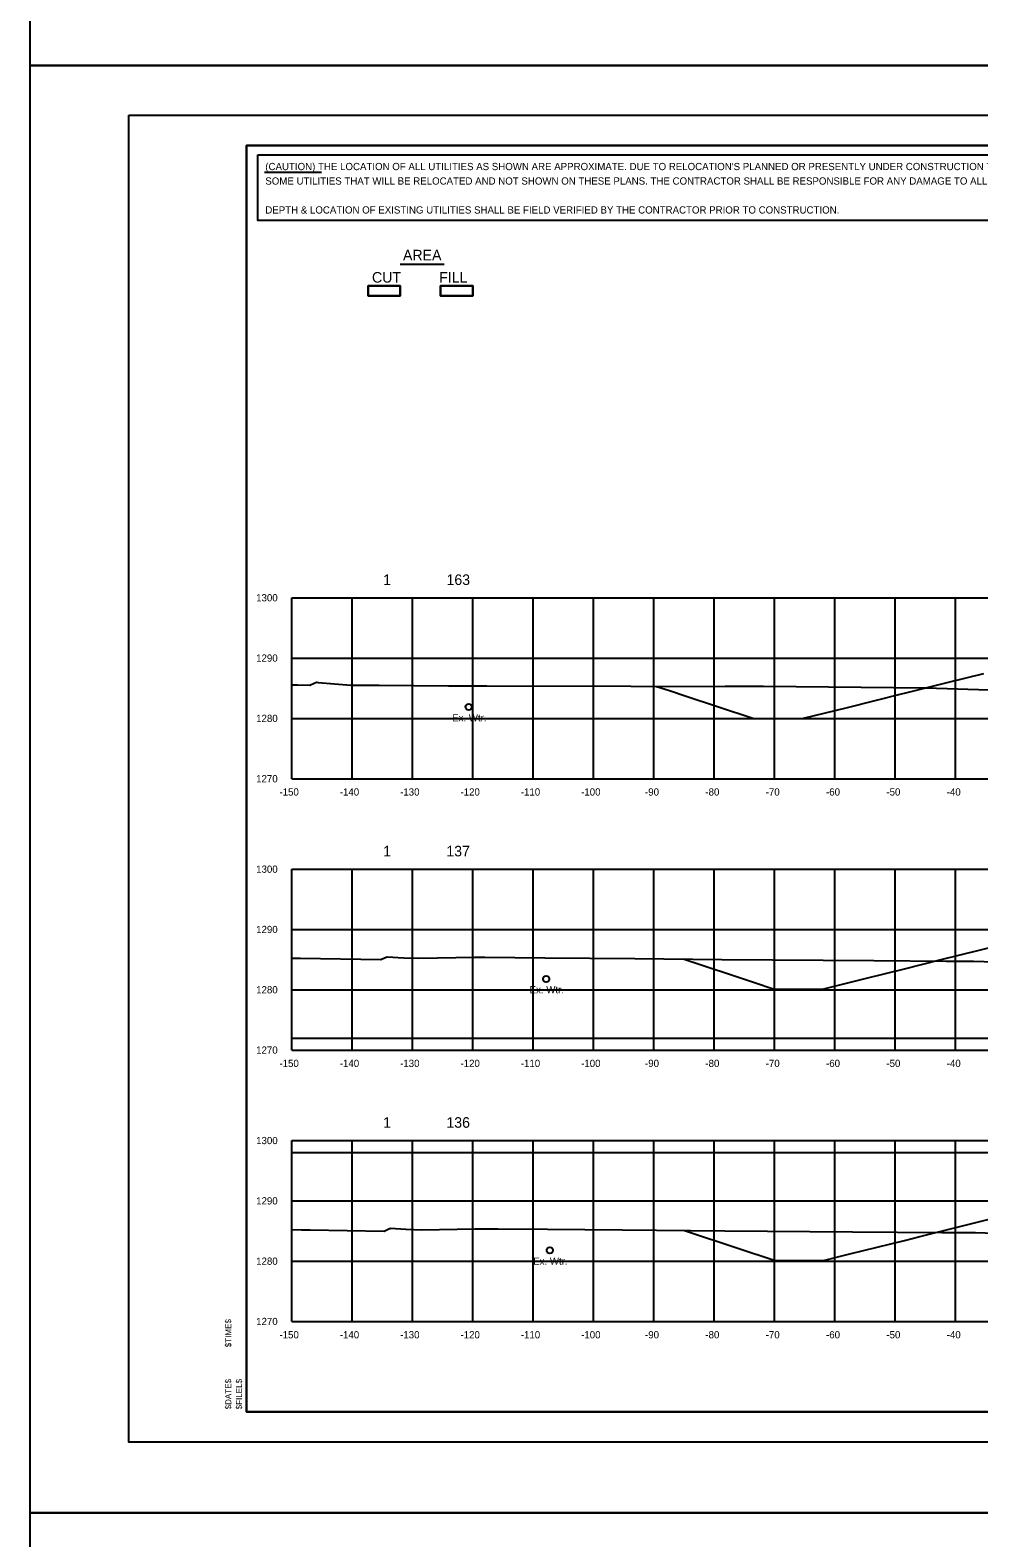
# Model space of a CAD drawing. Extents: x 2148105 to 2149976, y 144169 to 149705.
# Drawn here: x 2148219.9 to 2148377.2, y 144421 to 144671 of the extents above; entities that cross this region are included whole.
import ezdxf

# ---------------------------------------------------------------- set-up
doc = ezdxf.new("R2010")
doc.units = 0
for name, color, linetype in [('EX_Align', 7, 'Continuous'), ('PH1a-PR-Drives', 7, 'Continuous'), ('PH1a-PR-ServRd', 7, 'Continuous'), ('PH1a-TempConn-Shld', 7, 'Continuous'), ('PR_Align_PC', 7, 'Continuous'), ('PR_Align_Ramp_E', 7, 'Continuous'), ('PR_Align_Ramp_J', 7, 'Continuous'), ('PR_Storm_Conc_Box_PH1B', 7, 'Continuous'), ('PR_Storm_Conc_Pipe_PH1B', 7, 'Continuous'), ('PR_Storm_Inlet_CICI_PH1B', 7, 'Continuous'), ('PR_Storm_Junction_Box_PH1A', 7, 'Continuous'), ('PR_Storm_MH', 7, 'Continuous'), ('PR_Storm_MH_PH1B', 7, 'Continuous'), ('PR_Storm_Standard_Median_Drain_PH1B', 7, 'Continuous'), ('SURV_Benchmark', 7, 'Continuous'), ('TopCut', 7, 'Continuous'), ('TOPO_Asphalt', 7, 'Continuous'), ('TOPO_BRIDGE_Pier Cap', 7, 'Continuous')]:
    doc.layers.add(name, color=color, linetype=linetype)

msp = doc.modelspace()

# ---------------------------------------------------------------- linework, layer by layer
at = {"layer": 'EX_Align'}
for points in [[(2148323.77, 144562.22), (2148325.88, 144561.52), (2148328.67, 144560.6), (2148333.88, 144558.87), (2148339.89, 144556.87), (2148340.5, 144556.87), (2148342.6, 144556.87), (2148343.72, 144556.87), (2148343.91, 144556.87), (2148347.15, 144556.87), (2148347.92, 144556.87), (2148355.43, 144558.74), (2148364.35, 144560.97), (2148365.08, 144561.15), (2148366.16, 144561.42), (2148372.17, 144562.92), (2148377.99, 144564.37)], [(2148328.18, 144517.02), (2148339.97, 144513.1), (2148343.26, 144512), (2148346.06, 144512), (2148347.26, 144512), (2148349.86, 144512), (2148351.27, 144512), (2148358.53, 144513.82), (2148364.83, 144515.39), (2148370.71, 144516.86), (2148380.81, 144519.38), (2148381.26, 144519.36), (2148382.83, 144519.3), (2148384.48, 144519.23), (2148384.83, 144519.22), (2148385.47, 144519.19), (2148388.83, 144519.05), (2148389.99, 144519.01), (2148396.75, 144518.73), (2148400.83, 144518.56)], [(2148328.39, 144472.01), (2148337.21, 144469.07), (2148343.4, 144467.01), (2148345.29, 144467.01), (2148347.41, 144467.01), (2148349.09, 144467.01), (2148351.41, 144467.01), (2148355.8, 144468.11), (2148364.84, 144470.36), (2148367.38, 144471), (2148378.21, 144473.7), (2148379.56, 144474.04), (2148380.84, 144474.36), (2148382.35, 144474.29), (2148382.85, 144474.27), (2148384.13, 144474.22), (2148384.85, 144474.19), (2148386.78, 144474.11), (2148388.85, 144474.03), (2148391.34, 144473.92), (2148394.72, 144473.78), (2148399.86, 144473.57), (2148400.85, 144473.53)]]:
    msp.add_lwpolyline(points, dxfattribs=at)
at = {"layer": 'PH1a-PR-ServRd'}
msp.add_lwpolyline([(2148570.82, 144441.91), (2148255.82, 144441.91), (2148255.82, 144651.91), (2148570.82, 144651.91)], close=True, dxfattribs=at)
at = {"layer": 'PH1a-TempConn-Shld'}
msp.add_line((2148263.32, 144503.91), (2148563.32, 144503.91), dxfattribs=at)
at = {"layer": 'PR_Align_PC'}
msp.add_line((2148281.28, 144632.21), (2148288.56, 144632.21), dxfattribs=at)
for points in [[(2148275.98, 144628.66), (2148281.29, 144628.66), (2148281.29, 144626.97), (2148275.98, 144626.97)], [(2148275.98, 144628.66), (2148281.29, 144628.66), (2148281.29, 144626.97), (2148275.98, 144626.97)], [(2148287.98, 144628.66), (2148293.29, 144628.66), (2148293.29, 144626.97), (2148287.98, 144626.97)], [(2148287.98, 144628.66), (2148293.29, 144628.66), (2148293.29, 144626.97), (2148287.98, 144626.97)]]:
    msp.add_lwpolyline(points, close=True, dxfattribs=at)
at = {"layer": 'PR_Align_Ramp_E'}
for points in [[(2148219.95, 144905.16), (2148579.95, 144905.16), (2148579.95, 144665.16), (2148219.95, 144665.16)], [(2148219.95, 144665.16), (2148579.95, 144665.16), (2148579.95, 144425.16), (2148219.95, 144425.16)], [(2148219.95, 144425.16), (2148579.95, 144425.16), (2148579.95, 144185.16), (2148219.95, 144185.16)]]:
    msp.add_lwpolyline(points, close=True, dxfattribs=at)
at = {"layer": 'PR_Align_Ramp_J'}
msp.add_lwpolyline([(2148236.32, 144656.91), (2148576.32, 144656.91), (2148576.32, 144436.91), (2148236.32, 144436.91)], close=True, dxfattribs=at)
at = {"layer": 'PR_Storm_Conc_Box_PH1B'}
for p, q in [((2148263.32, 144576.91), (2148563.32, 144576.91)), ((2148263.32, 144546.91), (2148263.32, 144576.91)), ((2148273.32, 144546.91), (2148273.32, 144576.91)), ((2148283.32, 144546.91), (2148283.32, 144576.91)), ((2148293.32, 144546.91), (2148293.32, 144576.91)), ((2148303.32, 144546.91), (2148303.32, 144576.91)), ((2148313.32, 144546.91), (2148313.32, 144576.91)), ((2148323.32, 144546.91), (2148323.32, 144576.91)), ((2148333.32, 144546.91), (2148333.32, 144576.91)), ((2148343.32, 144546.91), (2148343.32, 144576.91)), ((2148353.32, 144546.91), (2148353.32, 144576.91)), ((2148363.32, 144546.91), (2148363.32, 144576.91)), ((2148373.32, 144546.91), (2148373.32, 144576.91)), ((2148263.32, 144566.91), (2148563.32, 144566.91)), ((2148263.32, 144556.91), (2148563.32, 144556.91)), ((2148263.32, 144546.91), (2148563.32, 144546.91)), ((2148263.32, 144531.91), (2148563.32, 144531.91)), ((2148263.32, 144501.91), (2148263.32, 144531.91)), ((2148273.32, 144501.91), (2148273.32, 144531.91)), ((2148283.32, 144501.91), (2148283.32, 144531.91)), ((2148293.32, 144501.91), (2148293.32, 144531.91)), ((2148303.32, 144501.91), (2148303.32, 144531.91)), ((2148313.32, 144501.91), (2148313.32, 144531.91)), ((2148323.32, 144501.91), (2148323.32, 144531.91)), ((2148333.32, 144501.91), (2148333.32, 144531.91)), ((2148343.32, 144501.91), (2148343.32, 144531.91)), ((2148353.32, 144501.91), (2148353.32, 144531.91)), ((2148363.32, 144501.91), (2148363.32, 144531.91)), ((2148373.32, 144501.91), (2148373.32, 144531.91)), ((2148263.32, 144521.91), (2148563.32, 144521.91)), ((2148263.32, 144511.91), (2148563.32, 144511.91)), ((2148263.32, 144501.91), (2148563.32, 144501.91)), ((2148263.32, 144456.91), (2148263.32, 144486.91)), ((2148273.32, 144456.91), (2148273.32, 144486.91)), ((2148283.32, 144456.91), (2148283.32, 144486.91)), ((2148293.32, 144456.91), (2148293.32, 144486.91)), ((2148303.32, 144456.91), (2148303.32, 144486.91)), ((2148313.32, 144456.91), (2148313.32, 144486.91)), ((2148323.32, 144456.91), (2148323.32, 144486.91)), ((2148333.32, 144456.91), (2148333.32, 144486.91)), ((2148343.32, 144456.91), (2148343.32, 144486.91)), ((2148353.32, 144456.91), (2148353.32, 144486.91)), ((2148363.32, 144456.91), (2148363.32, 144486.91)), ((2148373.32, 144456.91), (2148373.32, 144486.91)), ((2148263.32, 144476.91), (2148563.32, 144476.91)), ((2148263.32, 144466.91), (2148563.32, 144466.91)), ((2148263.32, 144456.91), (2148563.32, 144456.91))]:
    msp.add_line(p, q, dxfattribs=at)
at = {"layer": 'PR_Storm_Conc_Pipe_PH1B'}
msp.add_lwpolyline([(2148255.82, 144441.91), (2148570.82, 144441.91), (2148570.82, 144651.91), (2148255.82, 144651.91)], close=True, dxfattribs=at)
msp.add_lwpolyline([(2148255.82, 144441.91), (2148570.82, 144441.91), (2148570.82, 144651.91), (2148255.82, 144651.91)], close=True, dxfattribs=at)
at = {"layer": 'PR_Storm_Inlet_CICI_PH1B'}
for points in [[(2148263.32, 144562.49), (2148264.28, 144562.47), (2148266.3, 144562.43), (2148266.39, 144562.47), (2148267.39, 144562.92), (2148267.69, 144562.87), (2148273.09, 144562.42), (2148277.79, 144562.4), (2148289.26, 144562.32), (2148294.27, 144562.31), (2148295.63, 144562.3), (2148319.47, 144562.26), (2148325.53, 144562.21), (2148335.13, 144562.28), (2148337.19, 144562.27), (2148341.5, 144562.23), (2148368.44, 144561.95), (2148384.04, 144561.46)], [(2148263.32, 144517.17), (2148263.89, 144517.16), (2148264.35, 144517.15), (2148264.76, 144517.15), (2148278.06, 144516.91), (2148278.69, 144517.2), (2148279.14, 144517.4), (2148281.88, 144517.2), (2148284.35, 144517.14), (2148293.58, 144517.29), (2148295.31, 144517.29), (2148305.25, 144517.22), (2148320.18, 144517.11), (2148334.57, 144516.95), (2148359.77, 144516.76), (2148371.74, 144516.67), (2148376.29, 144516.65), (2148399.19, 144515.92)], [(2148263.32, 144472.15), (2148263.32, 144472.15), (2148264.92, 144472.13), (2148266.34, 144472.1), (2148278.61, 144471.89), (2148279.27, 144472.19), (2148279.68, 144472.38), (2148282.21, 144472.19), (2148284.85, 144472.13), (2148293.63, 144472.27), (2148297.51, 144472.27), (2148305.71, 144472.22), (2148318.07, 144472.12), (2148335.05, 144471.93), (2148356.21, 144471.77), (2148371.02, 144471.66), (2148376.64, 144471.64), (2148397.52, 144470.97)]]:
    msp.add_lwpolyline(points, dxfattribs=at)
at = {"layer": 'PR_Storm_Junction_Box_PH1A'}
for centre in [(2148292.63, 144558.8), (2148305.47, 144513.71), (2148306.07, 144468.7)]:
    msp.add_circle(centre, 0.516, dxfattribs=at)
at = {"layer": 'PR_Storm_MH'}
msp.add_line((2148258.8, 144647.46), (2148268.21, 144647.46), dxfattribs=at)
msp.add_lwpolyline([(2148257.69, 144650.34), (2148420.12, 144650.34), (2148420.12, 144639.47), (2148257.69, 144639.47)], close=True, dxfattribs=at)
at = {"layer": 'PR_Storm_Standard_Median_Drain_PH1B'}
for p, q in [((2148263.32, 144546.91), (2148263.32, 144576.91)), ((2148263.32, 144546.91), (2148563.32, 144546.91)), ((2148263.32, 144501.91), (2148263.32, 144531.91)), ((2148263.32, 144501.91), (2148563.32, 144501.91)), ((2148263.32, 144456.91), (2148263.32, 144486.91)), ((2148263.32, 144456.91), (2148563.32, 144456.91))]:
    msp.add_line(p, q, dxfattribs=at)
at = {"layer": 'SURV_Benchmark'}
msp.add_line((2148263.32, 144486.91), (2148563.32, 144486.91), dxfattribs=at)
at = {"layer": 'TopCut'}
msp.add_lwpolyline([(2148287.98, 144626.97), (2148293.29, 144626.97), (2148293.29, 144628.66), (2148287.98, 144628.66), (2148287.98, 144626.97)], dxfattribs=at)
at = {"layer": 'TOPO_Asphalt'}
msp.add_line((2148263.32, 144484.91), (2148563.32, 144484.91), dxfattribs=at)
at = {"layer": 'TOPO_BRIDGE_Pier Cap'}
msp.add_lwpolyline([(2148275.98, 144626.97), (2148281.29, 144626.97), (2148281.29, 144628.66), (2148275.98, 144628.66), (2148275.98, 144626.97)], dxfattribs=at)

# ---------------------------------------------------------------- texts
at = {"layer": 'PH1a-PR-Drives'}
for s, p in [('$TIME$', (2148253.27, 144452.63)), ('$DATE$', (2148253.27, 144442.33)), ('$FILEL$', (2148255.05, 144442.33))]:
    msp.add_text(s, height=1, rotation=90, dxfattribs=at).set_placement(p)
at = {"layer": 'PR_Align_PC'}
for s, p in [('AREA', (2148281.74, 144632.86)), ('CUT', (2148276.6, 144629.17)), ('FILL', (2148287.74, 144629.17)), ('1', (2148278.44, 144579.03)), ('163', (2148288.95, 144579.03)), ('1', (2148278.44, 144534.03)), ('137', (2148288.92, 144534.03)), ('1', (2148278.44, 144489.03)), ('136', (2148288.93, 144489.03))]:
    msp.add_text(s, height=1.75, dxfattribs=at).set_placement(p)
at = {"layer": 'PR_Storm_Junction_Box_PH1A'}
for p in [(2148289.88, 144556.41), (2148302.72, 144511.32), (2148303.31, 144466.31)]:
    msp.add_text('Ex. Wtr.', height=1.2, rotation=360, dxfattribs=at).set_placement(p)
at = {"layer": 'PR_Storm_MH'}
for s, p in [("(CAUTION) THE LOCATION OF ALL UTILITIES AS SHOWN ARE APPROXIMATE. DUE TO RELOCATION'S PLANNED OR PRESENTLY UNDER CONSTRUCTION THERE ARE ", (2148258.92, 144647.82)), ('SOME UTILITIES THAT WILL BE RELOCATED AND NOT SHOWN ON THESE PLANS. THE CONTRACTOR SHALL BE RESPONSIBLE FOR ANY DAMAGE TO ALL UTILITIES.', (2148258.92, 144645.42)), ('DEPTH & LOCATION OF EXISTING UTILITIES SHALL BE FIELD VERIFIED BY THE CONTRACTOR PRIOR TO CONSTRUCTION.', (2148258.92, 144640.62))]:
    msp.add_text(s, height=1.2, dxfattribs=at).set_placement(p)
at = {"layer": 'PR_Storm_MH_PH1B'}
for s, p in [('1300', (2148257.4, 144576.31)), ('1290', (2148257.4, 144566.31)), ('1280', (2148257.4, 144556.31)), ('1270', (2148257.4, 144546.31)), ('-150', (2148261.26, 144544.11)), ('-140', (2148271.26, 144544.11)), ('-130', (2148281.26, 144544.11)), ('-120', (2148291.26, 144544.11)), ('-110', (2148301.26, 144544.11)), ('-100', (2148311.26, 144544.11)), ('-90', (2148321.85, 144544.11)), ('-80', (2148331.85, 144544.11)), ('-70', (2148341.85, 144544.11)), ('-60', (2148351.85, 144544.11)), ('-50', (2148361.85, 144544.11)), ('-40', (2148371.85, 144544.11)), ('1300', (2148257.4, 144531.31)), ('1290', (2148257.4, 144521.31)), ('1280', (2148257.4, 144511.31)), ('1270', (2148257.4, 144501.31)), ('-150', (2148261.26, 144499.11)), ('-140', (2148271.26, 144499.11)), ('-130', (2148281.26, 144499.11)), ('-120', (2148291.26, 144499.11)), ('-110', (2148301.26, 144499.11)), ('-100', (2148311.26, 144499.11)), ('-90', (2148321.85, 144499.11)), ('-80', (2148331.85, 144499.11)), ('-70', (2148341.85, 144499.11)), ('-60', (2148351.85, 144499.11)), ('-50', (2148361.85, 144499.11)), ('-40', (2148371.85, 144499.11)), ('1300', (2148257.4, 144486.31)), ('1290', (2148257.4, 144476.31)), ('1280', (2148257.4, 144466.31)), ('1270', (2148257.4, 144456.31)), ('-150', (2148261.26, 144454.11)), ('-140', (2148271.26, 144454.11)), ('-130', (2148281.26, 144454.11)), ('-120', (2148291.26, 144454.11)), ('-110', (2148301.26, 144454.11)), ('-100', (2148311.26, 144454.11)), ('-90', (2148321.85, 144454.11)), ('-80', (2148331.85, 144454.11)), ('-70', (2148341.85, 144454.11)), ('-60', (2148351.85, 144454.11)), ('-50', (2148361.85, 144454.11)), ('-40', (2148371.85, 144454.11))]:
    msp.add_text(s, height=1.2, dxfattribs=at).set_placement(p)

doc.saveas('drawing.dxf')
